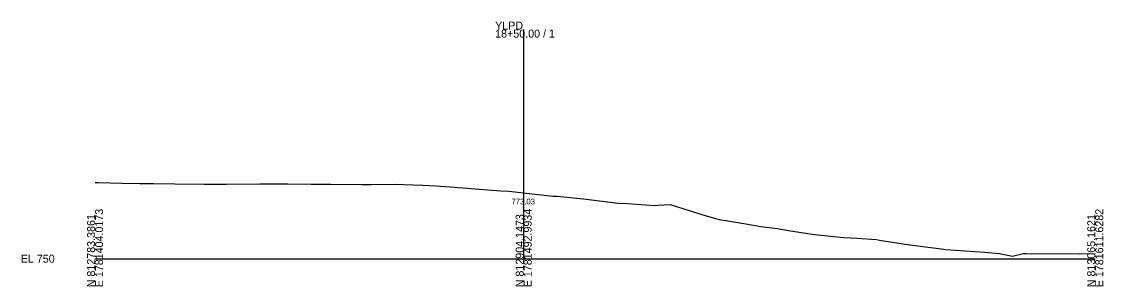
# Model space of a CAD drawing. Extents: x -26 to 353, y -10 to 9080.
# Drawn here: x -25.7 to 352.8, y 8490.3 to 8583 of the extents above; entities that cross this region are included whole.
import ezdxf

# ---------------------------------------------------------------- set-up
doc = ezdxf.new("R2010")
doc.units = 0
for name, color, linetype in [('Exist Cross Section Cell', 7, 'Continuous'), ('Exist XS Center Line Elevation Label', 7, 'Continuous'), ('Exist XS Ground Line', 7, 'Continuous')]:
    doc.layers.add(name, color=color, linetype=linetype)

msp = doc.modelspace()

# ---------------------------------------------------------------- linework, layer by layer
at = {"layer": 'Exist Cross Section Cell'}
for p, q in [((150, 8500), (150, 8580.23)), ((0, 8500), (150, 8500)), ((150, 8500), (350, 8500))]:
    msp.add_line(p, q, dxfattribs=at)
at = {"layer": 'Exist XS Ground Line'}
for p, q in [((0, 8526.74), (1.05, 8526.71)), ((1.05, 8526.71), (9.35, 8526.46)), ((9.35, 8526.46), (15.66, 8526.37)), ((15.66, 8526.37), (20.48, 8526.33)), ((20.48, 8526.33), (27.9, 8526.25)), ((27.9, 8526.25), (38.22, 8526.13)), ((38.22, 8526.13), (39.97, 8526.12)), ((39.97, 8526.12), (46.05, 8526.15)), ((46.05, 8526.15), (57.77, 8526.2)), ((57.77, 8526.2), (60.93, 8526.23)), ((60.93, 8526.23), (67.51, 8526.21)), ((67.51, 8526.21), (75.66, 8526.12)), ((75.66, 8526.12), (82.55, 8526.13)), ((82.55, 8526.13), (93.33, 8526)), ((93.33, 8526), (94.47, 8525.99)), ((94.47, 8525.99), (96.64, 8526)), ((96.64, 8526), (105.28, 8526.09)), ((105.28, 8526.09), (107.95, 8525.94)), ((107.95, 8525.94), (114.69, 8525.79)), ((114.69, 8525.79), (119.25, 8525.56)), ((119.25, 8525.56), (124.25, 8525.2)), ((124.25, 8525.2), (137.32, 8524.08)), ((137.32, 8524.08), (142.04, 8523.78)), ((142.04, 8523.78), (144.78, 8523.63)), ((144.78, 8523.63), (150, 8523.03)), ((150, 8523.03), (150.9, 8522.92)), ((150.9, 8522.92), (160.26, 8521.96)), ((160.26, 8521.96), (161.77, 8521.9)), ((161.77, 8521.9), (165.12, 8521.51)), ((165.12, 8521.51), (170.87, 8520.94)), ((170.87, 8520.94), (177.43, 8520.2)), ((177.43, 8520.2), (183.04, 8519.49)), ((183.04, 8519.49), (186.37, 8519.28)), ((186.37, 8519.28), (195.74, 8518.62)), ((195.74, 8518.62), (196.92, 8518.72)), ((196.92, 8518.72), (201.26, 8518.96)), ((201.26, 8518.96), (212.31, 8515.44)), ((212.31, 8515.44), (216.67, 8514.24)), ((216.67, 8514.24), (218.95, 8513.65)), ((218.95, 8513.65), (220.69, 8513.34)), ((220.69, 8513.34), (227.69, 8512.17)), ((227.69, 8512.17), (232.99, 8511.32)), ((232.99, 8511.32), (238.64, 8510.55)), ((238.64, 8510.55), (243.35, 8509.81)), ((243.35, 8509.81), (250.19, 8508.7)), ((250.19, 8508.7), (251.93, 8508.49)), ((251.93, 8508.49), (260.89, 8507.54)), ((260.89, 8507.54), (261.94, 8507.46)), ((261.94, 8507.46), (264.62, 8507.27)), ((264.62, 8507.27), (266.53, 8507.15)), ((266.53, 8507.15), (273.45, 8506.68)), ((273.45, 8506.68), (274.52, 8506.51)), ((274.52, 8506.51), (282.73, 8505.16)), ((282.73, 8505.16), (283.21, 8505.11)), ((283.21, 8505.11), (295.29, 8503.53)), ((295.29, 8503.53), (297.72, 8503.26)), ((297.72, 8503.26), (311.24, 8502.25)), ((311.24, 8502.25), (316.42, 8501.84)), ((316.42, 8501.84), (321.08, 8500.87)), ((321.08, 8500.87), (324.86, 8501.82)), ((324.86, 8501.82), (325.83, 8501.8)), ((325.83, 8501.8), (344.59, 8501.66)), ((344.59, 8501.66), (350, 8501.77))]:
    msp.add_line(p, q, dxfattribs=at)

# ---------------------------------------------------------------- texts
at = {"layer": 'Exist Cross Section Cell'}
for s, p in [('YLPD', (140, 8580.23)), ('18+50.00 / 1', (140, 8577.43)), ('EL 750', (-26, 8498.6))]:
    msp.add_text(s, height=2.8, dxfattribs=at).set_placement(p)
for s, p in [('E 1781404.0173', (2.8, 8490)), ('E 1781492.9934', (152.8, 8490)), ('E 1781611.6282', (352.8, 8490)), ('N 812783.3861', (0, 8490)), ('N 812904.1473', (150, 8490)), ('N 813065.1621', (350, 8490))]:
    msp.add_text(s, height=2.8, rotation=90, dxfattribs=at).set_placement(p)
at = {"layer": 'Exist XS Center Line Elevation Label'}
msp.add_text('773.03', height=2, dxfattribs=at).set_placement((145.75, 8519.03))

doc.saveas('drawing.dxf')
